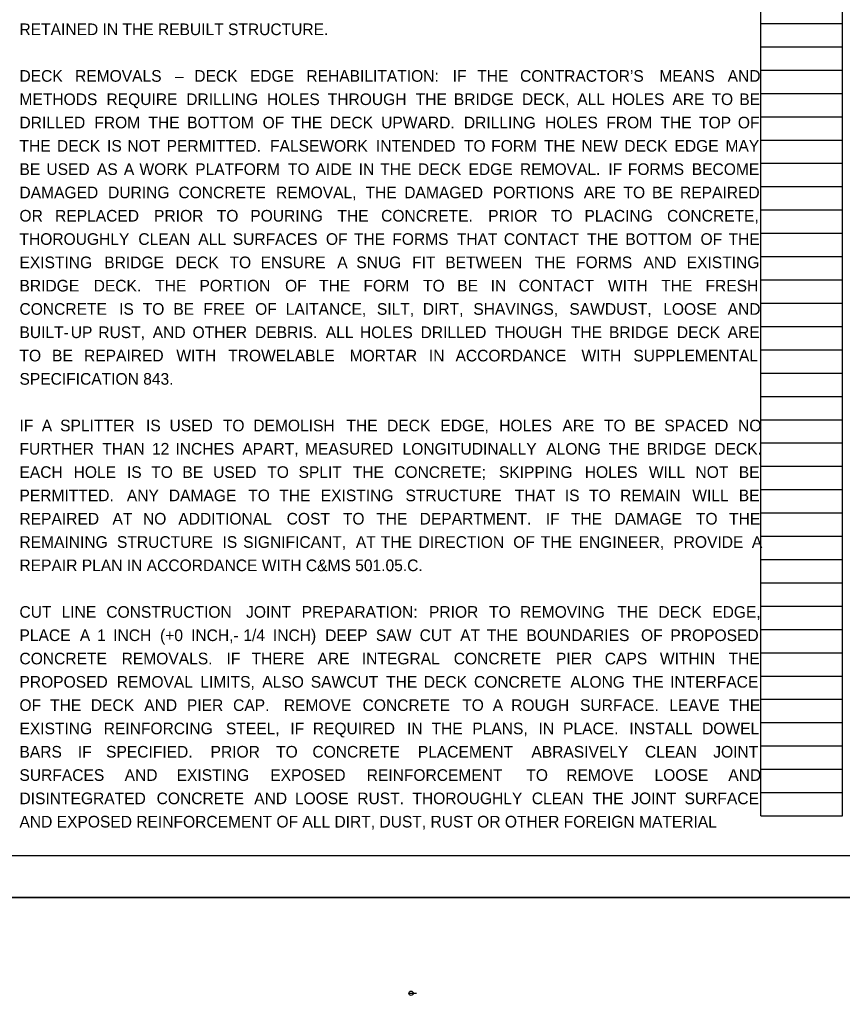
# Model space of a CAD drawing. Extents: x 0 to 44.4, y -4.7 to 22.
# Drawn here: x 12.29 to 22.19, y -1.18 to 10.55 of the extents above; entities that cross this region are included whole.
import ezdxf

# ---------------------------------------------------------------- set-up
doc = ezdxf.new("R2010")
doc.units = 0
for name, color, linetype in [('SC_Scratch1', 7, 'Continuous'), ('SH_Border', 7, 'Continuous'), ('SH_Cut_Line', 7, 'Continuous'), ('SH_Text', 7, 'Continuous')]:
    doc.layers.add(name, color=color, linetype=linetype)

msp = doc.modelspace()

# ---------------------------------------------------------------- linework, layer by layer
at = {"layer": 'SC_Scratch1'}
for p, q in [((21.207, 0.98), (21.207, 21.14)), ((22.187, 0.98), (22.187, 21.14)), ((21.207, 10.5), (22.187, 10.5)), ((21.207, 10.22), (22.187, 10.22)), ((21.207, 9.94), (22.187, 9.94)), ((21.207, 9.66), (22.187, 9.66)), ((21.207, 9.38), (22.187, 9.38)), ((21.207, 9.1), (22.187, 9.1)), ((21.207, 8.82), (22.187, 8.82)), ((21.207, 8.54), (22.187, 8.54)), ((21.207, 8.26), (22.187, 8.26)), ((21.207, 7.98), (22.187, 7.98)), ((21.207, 7.7), (22.187, 7.7)), ((21.207, 7.42), (22.187, 7.42)), ((21.207, 7.14), (22.187, 7.14)), ((21.207, 6.86), (22.187, 6.86)), ((21.207, 6.58), (22.187, 6.58)), ((21.207, 6.3), (22.187, 6.3)), ((21.207, 6.02), (22.187, 6.02)), ((21.207, 5.74), (22.187, 5.74)), ((21.207, 5.46), (22.187, 5.46)), ((21.207, 5.18), (22.187, 5.18)), ((21.207, 4.9), (22.187, 4.9)), ((21.207, 4.62), (22.187, 4.62)), ((21.207, 4.34), (22.187, 4.34)), ((21.207, 4.06), (22.187, 4.06)), ((21.207, 3.78), (22.187, 3.78)), ((21.207, 3.5), (22.187, 3.5)), ((21.207, 3.22), (22.187, 3.22)), ((21.207, 2.94), (22.187, 2.94)), ((21.207, 2.66), (22.187, 2.66)), ((21.207, 2.38), (22.187, 2.38)), ((21.207, 2.1), (22.187, 2.1)), ((21.207, 1.82), (22.187, 1.82)), ((21.207, 1.54), (22.187, 1.54)), ((21.207, 1.26), (22.187, 1.26)), ((21.207, 0.98), (22.187, 0.98))]:
    msp.add_line(p, q, dxfattribs=at)
msp.add_lwpolyline([(0, 22), (34, 22), (34, 0), (0, 0)], close=True, dxfattribs=at)
at = {"layer": 'SH_Border'}
msp.add_lwpolyline([(1.5, 21.5), (33.5, 21.5), (33.5, 0.5), (1.5, 0.5)], close=True, dxfattribs=at)
at = {"layer": 'SH_Cut_Line'}
msp.add_lwpolyline([(0, 0), (34, 0), (34, 22), (0, 22)], close=True, dxfattribs=at)
at = {"layer": 'SH_Text'}
for p, q in [((16.974, -1.152), (17.026, -1.152)), ((17, -1.152), (17.067, -1.152))]:
    msp.add_line(p, q, dxfattribs=at)
msp.add_circle((17, -1.152), 0.026, dxfattribs=at)

# ---------------------------------------------------------------- texts
for s, height, p in [('RETAINED IN THE REBUILT STRUCTURE.', 0.14, (12.293, 10.36)), ('DECK ', 0.14, (12.293, 9.8)), ('REMOVALS ', 0.14, (12.961, 9.8)), ('– ', 0.14, (14.162, 9.8)), ('DECK ', 0.14, (14.395, 9.8)), ('EDGE ', 0.14, (15.063, 9.8)), ('REHABILITATION: ', 0.14, (15.742, 9.8)), ('IF ', 0.14, (17.501, 9.8)), ('THE ', 0.14, (17.795, 9.8)), ('CONTRACTOR’S ', 0.14, (18.311, 9.8)), ('MEANS ', 0.14, (19.986, 9.8)), ('AND ', 0.14, (20.806, 9.8)), ('METHODS ', 0.14, (12.293, 9.52)), ('REQUIRE ', 0.14, (13.339, 9.52)), ('DRILLING ', 0.14, (14.298, 9.52)), ('HOLES ', 0.14, (15.268, 9.52)), ('THROUGH ', 0.14, (15.999, 9.52)), ('THE ', 0.14, (17.056, 9.52)), ('BRIDGE ', 0.14, (17.515, 9.52)), ('DECK, ', 0.14, (18.333, 9.52)), ('ALL ', 0.14, (18.998, 9.52)), ('HOLES ', 0.14, (19.411, 9.52)), ('ARE ', 0.14, (20.142, 9.52)), ('TO ', 0.14, (20.612, 9.52)), ('BE ', 0.14, (20.947, 9.52)), ('FROM ', 0.14, (13.193, 9.24)), ('BOTTOM ', 0.14, (14.309, 9.24)), ('OF ', 0.14, (15.216, 9.24)), ('DECK ', 0.14, (16.023, 9.24)), ('DRILLING ', 0.14, (17.635, 9.24)), ('HOLES ', 0.14, (18.611, 9.24)), ('FROM ', 0.14, (19.348, 9.24)), ('TOP ', 0.14, (20.463, 9.24)), ('OF ', 0.14, (20.929, 9.24)), ('DRILLED ', 0.14, (12.293, 9.24)), ('THE ', 0.14, (13.843, 9.24)), ('THE ', 0.14, (15.558, 9.24)), ('UPWARD. ', 0.14, (16.641, 9.24)), ('THE ', 0.14, (19.998, 9.24)), ('THE ', 0.14, (12.293, 8.96)), ('DECK ', 0.14, (12.744, 8.96)), ('IS ', 0.14, (13.346, 8.96)), ('NOT ', 0.14, (13.59, 8.96)), ('PERMITTED. ', 0.14, (14.062, 8.96)), ('FALSEWORK ', 0.14, (15.305, 8.96)), ('INTENDED ', 0.14, (16.578, 8.96)), ('TO ', 0.14, (17.637, 8.96)), ('FORM ', 0.14, (17.964, 8.96)), ('THE ', 0.14, (18.599, 8.96)), ('NEW ', 0.14, (19.049, 8.96)), ('DECK ', 0.14, (19.564, 8.96)), ('EDGE ', 0.14, (20.167, 8.96)), ('MAY ', 0.14, (20.78, 8.96)), ('BE ', 0.14, (12.293, 8.68)), ('USED ', 0.14, (12.617, 8.68)), ('AS ', 0.14, (13.224, 8.68)), ('A ', 0.14, (13.548, 8.68)), ('WORK ', 0.14, (13.735, 8.68)), ('PLATFORM ', 0.14, (14.406, 8.68)), ('TO ', 0.14, (15.52, 8.68)), ('AIDE ', 0.14, (15.852, 8.68)), ('IN ', 0.14, (16.371, 8.68)), ('THE ', 0.14, (16.63, 8.68)), ('DECK ', 0.14, (17.084, 8.68)), ('EDGE ', 0.14, (17.691, 8.68)), ('REMOVAL. ', 0.14, (18.309, 8.68)), ('IF ', 0.14, (19.372, 8.68)), ('FORMS ', 0.14, (19.606, 8.68)), ('BECOME ', 0.14, (20.375, 8.68)), ('DAMAGED ', 0.14, (12.293, 8.4)), ('DURING ', 0.14, (13.358, 8.4)), ('CONCRETE ', 0.14, (14.204, 8.4)), ('REMOVAL, ', 0.14, (15.377, 8.4)), ('THE ', 0.14, (16.453, 8.4)), ('DAMAGED ', 0.14, (16.919, 8.4)), ('PORTIONS ', 0.14, (17.983, 8.4)), ('ARE ', 0.14, (19.077, 8.4)), ('TO ', 0.14, (19.554, 8.4)), ('BE ', 0.14, (19.898, 8.4)), ('REPAIRED ', 0.14, (20.234, 8.4)), ('OR ', 0.14, (12.293, 8.12)), ('REPLACED ', 0.14, (12.721, 8.12)), ('PRIOR ', 0.14, (13.911, 8.12)), ('TO ', 0.14, (14.665, 8.12)), ('POURING ', 0.14, (15.068, 8.12)), ('THE ', 0.14, (16.115, 8.12)), ('CONCRETE. ', 0.14, (16.641, 8.12)), ('PRIOR ', 0.14, (17.928, 8.12)), ('TO ', 0.14, (18.682, 8.12)), ('PLACING ', 0.14, (19.085, 8.12)), ('CONCRETE, ', 0.14, (20.078, 8.12)), ('THOROUGHLY ', 0.14, (12.293, 7.84)), ('CLEAN ', 0.14, (13.722, 7.84)), ('ALL ', 0.14, (14.443, 7.84)), ('SURFACES ', 0.14, (14.857, 7.84)), ('OF ', 0.14, (15.977, 7.84)), ('THE ', 0.14, (16.314, 7.84)), ('FORMS ', 0.14, (16.775, 7.84)), ('THAT ', 0.14, (17.551, 7.84)), ('CONTACT ', 0.14, (18.116, 7.84)), ('THE ', 0.14, (19.117, 7.84)), ('BOTTOM ', 0.14, (19.577, 7.84)), ('OF ', 0.14, (20.48, 7.84)), ('THE ', 0.14, (20.817, 7.84)), ('EXISTING ', 0.14, (12.293, 7.56)), ('BRIDGE ', 0.14, (13.312, 7.56)), ('DECK ', 0.14, (14.168, 7.56)), ('TO ', 0.14, (14.818, 7.56)), ('ENSURE ', 0.14, (15.192, 7.56)), ('A ', 0.14, (16.113, 7.56)), ('SNUG ', 0.14, (16.342, 7.56)), ('FIT ', 0.14, (17.013, 7.56)), ('BETWEEN ', 0.14, (17.412, 7.56)), ('THE ', 0.14, (18.486, 7.56)), ('FORMS ', 0.14, (18.983, 7.56)), ('AND ', 0.14, (19.795, 7.56)), ('EXISTING ', 0.14, (20.314, 7.56)), ('BRIDGE ', 0.14, (12.293, 7.28)), ('DECK. ', 0.14, (13.185, 7.28)), ('THE ', 0.14, (13.924, 7.28)), ('PORTION ', 0.14, (14.457, 7.28)), ('OF ', 0.14, (15.486, 7.28)), ('THE ', 0.14, (15.895, 7.28)), ('FORM ', 0.14, (16.428, 7.28)), ('TO ', 0.14, (17.145, 7.28)), ('BE ', 0.14, (17.555, 7.28)), ('IN ', 0.14, (17.957, 7.28)), ('CONTACT ', 0.14, (18.294, 7.28)), ('WITH ', 0.14, (19.367, 7.28)), ('THE ', 0.14, (20.008, 7.28)), ('FRESH ', 0.14, (20.54, 7.28)), ('CONCRETE ', 0.14, (12.293, 7)), ('IS ', 0.14, (13.491, 7)), ('TO ', 0.14, (13.775, 7)), ('BE ', 0.14, (14.143, 7)), ('FREE ', 0.14, (14.504, 7)), ('OF ', 0.14, (15.126, 7)), ('LAITANCE, ', 0.14, (15.494, 7)), ('SILT, ', 0.14, (16.59, 7)), ('DIRT, ', 0.14, (17.142, 7)), ('SHAVINGS, ', 0.14, (17.749, 7)), ('SAWDUST, ', 0.14, (18.904, 7)), ('LOOSE ', 0.14, (20.032, 7)), ('AND ', 0.14, (20.806, 7)), ('BUILT-', 0.14, (12.293, 6.72)), ('UP ', 0.14, (12.91, 6.72)), ('RUST, ', 0.14, (13.241, 6.72)), ('AND ', 0.14, (13.895, 6.72)), ('OTHER ', 0.14, (14.374, 6.72)), ('DEBRIS. ', 0.14, (15.125, 6.72)), ('ALL ', 0.14, (15.975, 6.72)), ('HOLES ', 0.14, (16.386, 6.72)), ('DRILLED ', 0.14, (17.115, 6.72)), ('THOUGH ', 0.14, (18.008, 6.72)), ('THE ', 0.14, (18.922, 6.72)), ('BRIDGE ', 0.14, (19.38, 6.72)), ('DECK ', 0.14, (20.196, 6.72)), ('ARE ', 0.14, (20.806, 6.72)), ('TO ', 0.14, (12.293, 6.44)), ('BE ', 0.14, (12.685, 6.44)), ('REPAIRED ', 0.14, (13.069, 6.44)), ('WITH ', 0.14, (14.179, 6.44)), ('TROWELABLE ', 0.14, (14.802, 6.44)), ('MORTAR ', 0.14, (16.262, 6.44)), ('IN ', 0.14, (17.215, 6.44)), ('ACCORDANCE ', 0.14, (17.535, 6.44)), ('WITH ', 0.14, (19.049, 6.44)), ('SUPPLEMENTAL ', 0.14, (19.673, 6.44)), ('SPECIFICATION 843.', 0.14, (12.293, 6.16)), ('IF ', 0.14, (12.293, 5.6)), ('A ', 0.14, (12.561, 5.6)), ('SPLITTER ', 0.14, (12.782, 5.6)), ('IS ', 0.14, (13.814, 5.6)), ('USED ', 0.14, (14.097, 5.6)), ('TO ', 0.14, (14.738, 5.6)), ('DEMOLISH ', 0.14, (15.104, 5.6)), ('THE ', 0.14, (16.223, 5.6)), ('DECK ', 0.14, (16.712, 5.6)), ('EDGE, ', 0.14, (17.353, 5.6)), ('HOLES ', 0.14, (18.06, 5.6)), ('ARE ', 0.14, (18.82, 5.6)), ('TO ', 0.14, (19.32, 5.6)), ('BE ', 0.14, (19.686, 5.6)), ('SPACED ', 0.14, (20.045, 5.6)), ('NO ', 0.14, (20.932, 5.6)), ('FURTHER ', 0.14, (12.293, 5.32)), ('THAN ', 0.14, (13.289, 5.32)), ('12 ', 0.14, (13.886, 5.32)), ('INCHES ', 0.14, (14.168, 5.32)), ('APART, ', 0.14, (14.972, 5.32)), ('MEASURED ', 0.14, (15.725, 5.32)), ('LONGITUDINALLY ', 0.14, (16.898, 5.32)), ('ALONG ', 0.14, (18.626, 5.32)), ('THE ', 0.14, (19.376, 5.32)), ('BRIDGE ', 0.14, (19.832, 5.32)), ('DECK. ', 0.14, (20.646, 5.32)), ('EACH ', 0.14, (12.293, 5.04)), ('HOLE ', 0.14, (12.944, 5.04)), ('IS ', 0.14, (13.585, 5.04)), ('TO ', 0.14, (13.877, 5.04)), ('BE ', 0.14, (14.252, 5.04)), ('USED ', 0.14, (14.621, 5.04)), ('TO ', 0.14, (15.272, 5.04)), ('SPLIT ', 0.14, (15.648, 5.04)), ('THE ', 0.14, (16.299, 5.04)), ('CONCRETE; ', 0.14, (16.798, 5.04)), ('SKIPPING ', 0.14, (18.057, 5.04)), ('HOLES ', 0.14, (19.089, 5.04)), ('WILL ', 0.14, (19.859, 5.04)), ('NOT ', 0.14, (20.42, 5.04)), ('BE ', 0.14, (20.94, 5.04)), ('PERMITTED. ', 0.14, (12.293, 4.76)), ('ANY ', 0.14, (13.584, 4.76)), ('DAMAGE ', 0.14, (14.089, 4.76)), ('TO ', 0.14, (15.043, 4.76)), ('THE ', 0.14, (15.417, 4.76)), ('EXISTING ', 0.14, (15.915, 4.76)), ('STRUCTURE ', 0.14, (16.934, 4.76)), ('THAT ', 0.14, (18.247, 4.76)), ('IS ', 0.14, (18.849, 4.76)), ('TO ', 0.14, (19.14, 4.76)), ('REMAIN ', 0.14, (19.514, 4.76)), ('WILL ', 0.14, (20.381, 4.76)), ('BE ', 0.14, (20.94, 4.76)), ('REPAIRED ', 0.14, (12.293, 4.48)), ('AT ', 0.14, (13.411, 4.48)), ('NO ', 0.14, (13.778, 4.48)), ('ADDITIONAL ', 0.14, (14.203, 4.48)), ('COST ', 0.14, (15.505, 4.48)), ('TO ', 0.14, (16.181, 4.48)), ('THE ', 0.14, (16.581, 4.48)), ('DEPARTMENT. ', 0.14, (17.104, 4.48)), ('IF ', 0.14, (18.62, 4.48)), ('THE ', 0.14, (18.922, 4.48)), ('DAMAGE ', 0.14, (19.445, 4.48)), ('TO ', 0.14, (20.425, 4.48)), ('THE ', 0.14, (20.824, 4.48)), ('REMAINING ', 0.14, (12.293, 4.2)), ('STRUCTURE ', 0.14, (13.465, 4.2)), ('IS ', 0.14, (14.734, 4.2)), ('SIGNIFICANT, ', 0.14, (14.982, 4.2)), ('AT ', 0.14, (16.338, 4.2)), ('THE ', 0.14, (16.636, 4.2)), ('DIRECTION ', 0.14, (17.09, 4.2)), ('OF ', 0.14, (18.229, 4.2)), ('THE ', 0.14, (18.56, 4.2)), ('ENGINEER, ', 0.14, (19.014, 4.2)), ('PROVIDE ', 0.14, (20.153, 4.2)), ('A ', 0.14, (21.097, 4.2)), ('REPAIR PLAN IN ACCORDANCE WITH C&MS 501.05.C. ', 0.14, (12.293, 3.92)), ('CUT ', 0.14, (12.293, 3.36)), ('LINE ', 0.14, (12.799, 3.36)), ('CONSTRUCTION ', 0.14, (13.337, 3.36)), ('JOINT ', 0.14, (15.017, 3.36)), ('PREPARATION: ', 0.14, (15.685, 3.36)), ('PRIOR ', 0.14, (17.216, 3.36)), ('TO ', 0.14, (17.939, 3.36)), ('REMOVING ', 0.14, (18.311, 3.36)), ('THE ', 0.14, (19.48, 3.36)), ('DECK ', 0.14, (19.974, 3.36)), ('EDGE, ', 0.14, (20.621, 3.36)), ('PLACE ', 0.14, (12.293, 3.08)), ('A ', 0.14, (13.019, 3.08)), ('1 ', 0.14, (13.227, 3.08)), ('INCH ', 0.14, (13.42, 3.08)), ('(+0 ', 0.14, (13.983, 3.08)), ('INCH,-', 0.14, (14.356, 3.08)), ('1/4 ', 0.14, (14.984, 3.08)), ('INCH) ', 0.14, (15.34, 3.08)), ('DEEP ', 0.14, (15.968, 3.08)), ('SAW ', 0.14, (16.578, 3.08)), ('CUT ', 0.14, (17.104, 3.08)), ('AT ', 0.14, (17.591, 3.08)), ('THE ', 0.14, (17.911, 3.08)), ('BOUNDARIES ', 0.14, (18.387, 3.08)), ('OF ', 0.14, (19.765, 3.08)), ('PROPOSED ', 0.14, (20.118, 3.08)), ('CONCRETE ', 0.14, (12.293, 2.8)), ('REMOVALS. ', 0.14, (13.521, 2.8)), ('IF ', 0.14, (14.782, 2.8)), ('THERE ', 0.14, (15.083, 2.8)), ('ARE ', 0.14, (15.876, 2.8)), ('INTEGRAL ', 0.14, (16.409, 2.8)), ('CONCRETE ', 0.14, (17.514, 2.8)), ('PIER ', 0.14, (18.742, 2.8)), ('CAPS ', 0.14, (19.329, 2.8)), ('WITHIN ', 0.14, (19.992, 2.8)), ('THE ', 0.14, (20.817, 2.8)), ('PROPOSED ', 0.14, (12.293, 2.52)), ('REMOVAL ', 0.14, (13.463, 2.52)), ('LIMITS, ', 0.14, (14.467, 2.52)), ('ALSO ', 0.14, (15.212, 2.52)), ('SAWCUT ', 0.14, (15.795, 2.52)), ('THE ', 0.14, (16.7, 2.52)), ('DECK ', 0.14, (17.153, 2.52)), ('CONCRETE ', 0.14, (17.757, 2.52)), ('ALONG ', 0.14, (18.916, 2.52)), ('THE ', 0.14, (19.662, 2.52)), ('INTERFACE ', 0.14, (20.114, 2.52)), ('OF ', 0.14, (12.293, 2.24)), ('THE ', 0.14, (12.661, 2.24)), ('DECK ', 0.14, (13.151, 2.24)), ('AND ', 0.14, (13.793, 2.24)), ('PIER ', 0.14, (14.306, 2.24)), ('CAP.  ', 0.14, (14.861, 2.24)), ('REMOVE ', 0.14, (15.471, 2.24)), ('CONCRETE ', 0.14, (16.418, 2.24)), ('TO ', 0.14, (17.615, 2.24)), ('A ', 0.14, (17.982, 2.24)), ('ROUGH ', 0.14, (18.204, 2.24)), ('SURFACE. ', 0.14, (19.032, 2.24)), ('LEAVE ', 0.14, (20.105, 2.24)), ('THE ', 0.14, (20.824, 2.24)), ('EXISTING ', 0.14, (12.293, 1.96)), ('REINFORCING ', 0.14, (13.306, 1.96)), ('STEEL, ', 0.14, (14.775, 1.96)), ('IF ', 0.14, (15.549, 1.96)), ('REQUIRED ', 0.14, (15.819, 1.96)), ('IN ', 0.14, (16.951, 1.96)), ('THE ', 0.14, (17.246, 1.96)), ('PLANS, ', 0.14, (17.737, 1.96)), ('IN ', 0.14, (18.533, 1.96)), ('PLACE. ', 0.14, (18.828, 1.96)), ('INSTALL ', 0.14, (19.624, 1.96)), ('DOWEL ', 0.14, (20.499, 1.96)), ('BARS ', 0.14, (12.293, 1.68)), ('IF ', 0.14, (12.995, 1.68)), ('SPECIFIED. ', 0.14, (13.334, 1.68)), ('PRIOR ', 0.14, (14.59, 1.68)), ('TO ', 0.14, (15.378, 1.68)), ('CONCRETE ', 0.14, (15.815, 1.68)), ('PLACEMENT ', 0.14, (17.082, 1.68)), ('ABRASIVELY ', 0.14, (18.447, 1.68)), ('CLEAN ', 0.14, (19.812, 1.68)), ('JOINT ', 0.14, (20.633, 1.68)), ('SURFACES ', 0.14, (12.293, 1.4)), ('AND ', 0.14, (13.557, 1.4)), ('EXISTING ', 0.14, (14.182, 1.4)), ('EXPOSED ', 0.14, (15.308, 1.4)), ('REINFORCEMENT ', 0.14, (16.467, 1.4)), ('TO ', 0.14, (18.386, 1.4)), ('REMOVE ', 0.14, (18.866, 1.4)), ('LOOSE ', 0.14, (19.927, 1.4)), ('AND ', 0.14, (20.814, 1.4)), ('DISINTEGRATED ', 0.14, (12.293, 1.12)), ('CONCRETE ', 0.14, (13.942, 1.12)), ('AND ', 0.14, (15.115, 1.12)), ('LOOSE ', 0.14, (15.604, 1.12)), ('RUST. ', 0.14, (16.354, 1.12)), ('THOROUGHLY ', 0.14, (17.017, 1.12)), ('CLEAN ', 0.14, (18.452, 1.12)), ('THE ', 0.14, (19.18, 1.12)), ('JOINT ', 0.14, (19.647, 1.12)), ('SURFACE ', 0.14, (20.288, 1.12)), ('AND EXPOSED REINFORCEMENT OF ALL DIRT, DUST, RUST OR OTHER FOREIGN MATERIAL ', 0.14, (12.293, 0.84)), ('P.17', 0.00328, (16.995, -1.162)), ('2', 0.00328, (16.999, -1.146)), ('Drawing - Copy-1', 0.00328, (17.032, -1.146)), ('1:1', 0.00328, (17.032, -1.162))]:
    msp.add_text(s, height=height, dxfattribs=at).set_placement(p)

doc.saveas('drawing.dxf')
